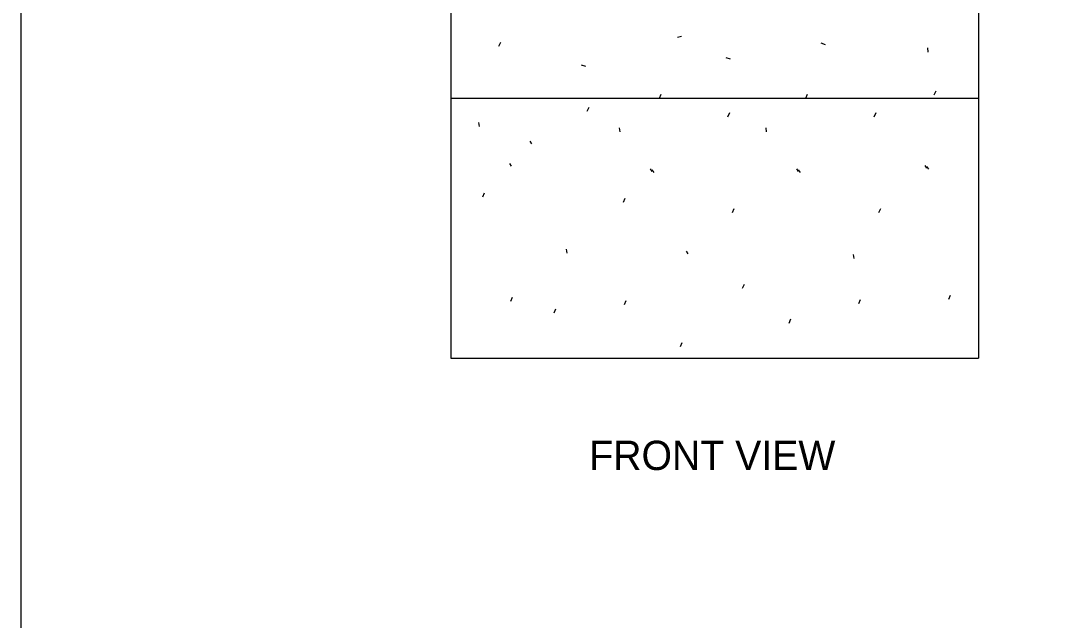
# Model space of a CAD drawing. Extents: x 99862 to 103151, y 100000 to 102076.
# Drawn here: x 99862 to 100576, y 101138 to 101547 of the extents above; entities that cross this region are included whole.
import ezdxf

# ---------------------------------------------------------------- set-up
doc = ezdxf.new("R2010")
doc.units = 0
for name, color, linetype in [('Level 1', 7, 'Continuous'), ('Level 20', 7, 'Continuous'), ('Level 7', 7, 'Continuous')]:
    doc.layers.add(name, color=color, linetype=linetype)

msp = doc.modelspace()

# ---------------------------------------------------------------- linework, layer by layer
at = {"layer": 'Level 1'}
msp.add_lwpolyline([(99862, 99999.5), (103151, 99999.5), (103151, 102075.5), (99862, 102075.5)], close=True, dxfattribs=at)
at = {"layer": 'Level 7'}
for p, q in [((100155.17, 101556.57), (100155.17, 101316.57)), ((100515.17, 101556.57), (100515.17, 101316.57)), ((100312.66, 101536.05), (100309.94, 101535.42)), ((100188.03, 101529.48), (100189.28, 101532.25)), ((100407.74, 101531.7), (100410.61, 101530.76)), ((100480.4, 101528.28), (100480.75, 101525.52)), ((100342.97, 101521.73), (100345.86, 101520.78)), ((100244.29, 101516.74), (100247.16, 101515.8)), ((100485.04, 101496.35), (100486.29, 101499.12)), ((100155.17, 101494.11), (100515.17, 101494.11)), ((100297.62, 101494.06), (100298.86, 101496.83)), ((100397.45, 101494.06), (100398.7, 101496.83)), ((100248.29, 101485.14), (100249.54, 101487.91)), ((100174.2, 101477.46), (100174.54, 101474.69)), ((100344.32, 101481.41), (100345.56, 101484.17)), ((100444.15, 101481.41), (100445.4, 101484.17)), ((100270.22, 101473.73), (100270.57, 101470.96)), ((100370.06, 101473.73), (100370.4, 101470.96)), ((100209.15, 101464.69), (100210.4, 101462.89)), ((100195.23, 101449.51), (100196.4, 101447.71)), ((100291.25, 101445.78), (100292.43, 101443.98)), ((100292.43, 101445.08), (100293.67, 101443.28)), ((100391.09, 101445.78), (100392.26, 101443.98)), ((100392.26, 101445.08), (100393.51, 101443.28)), ((100478.68, 101448.06), (100479.85, 101446.26)), ((100479.85, 101447.37), (100481.1, 101445.57)), ((100177.03, 101426.75), (100178.28, 101429.52)), ((100273.06, 101423.02), (100274.3, 101425.78)), ((100347.43, 101415.96), (100348.67, 101418.72)), ((100447.26, 101415.96), (100448.51, 101418.72)), ((100233.97, 101391.05), (100234.32, 101388.28)), ((100315.76, 101389.57), (100316.93, 101387.77)), ((100429.83, 101387.32), (100430.18, 101384.55)), ((100354.35, 101364.41), (100355.59, 101367.18)), ((100196.12, 101355.42), (100197.37, 101358.19)), ((100273.75, 101353.21), (100274.99, 101355.98)), ((100433.5, 101353.97), (100434.74, 101356.73)), ((100494.93, 101356.94), (100496.18, 101359.71)), ((100225.7, 101347.65), (100226.94, 101350.41)), ((100386.09, 101340.63), (100387.33, 101343.39)), ((100311.91, 101324.59), (100313.15, 101327.35)), ((100155.17, 101316.57), (100515.17, 101316.57))]:
    msp.add_line(p, q, dxfattribs=at)

# ---------------------------------------------------------------- texts
at = {"layer": 'Level 20'}
msp.add_text('FRONT VIEW', height=20, dxfattribs=at).set_placement((100249.71, 101240.33))

doc.saveas('drawing.dxf')
